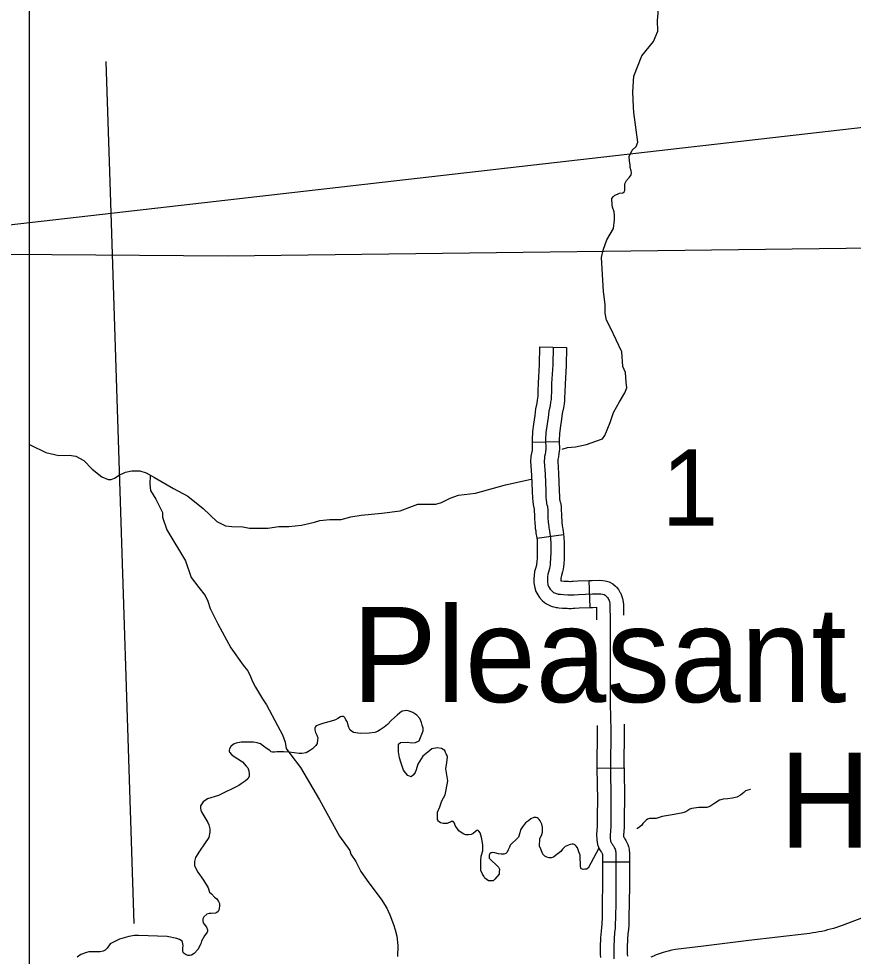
# Model space of a CAD drawing. Extents: x 1720274 to 1751788, y 372074 to 391887.
# Drawn here: x 1729981 to 1730713, y 376192 to 377014 of the extents above; entities that cross this region are included whole.
import ezdxf

# ---------------------------------------------------------------- set-up
doc = ezdxf.new("R2010")
doc.units = 0
for name, color, linetype in [('Level 10', 7, 'Continuous'), ('Level 24', 7, 'Continuous'), ('Level 32', 7, 'Continuous'), ('Level 35', 7, 'Continuous'), ('Level 43', 7, 'Continuous'), ('Level 5', 7, 'Continuous'), ('R_Draft', 7, 'Continuous')]:
    doc.layers.add(name, color=color, linetype=linetype)

msp = doc.modelspace()

# ---------------------------------------------------------------- linework, layer by layer
at = {"layer": 'Level 10'}
msp.add_lwpolyline([(1730737.54, 376231.42), (1730706.22, 376219.51), (1730703.68, 376218.58), (1730701.18, 376217.72), (1730698.66, 376216.91), (1730696.12, 376216.14), (1730693.57, 376215.41), (1730691.01, 376214.74), (1730688.43, 376214.11), (1730685.85, 376213.53), (1730683.25, 376213), (1730680.64, 376212.52), (1730678.03, 376212.08), (1730675.41, 376211.7), (1730672.74, 376211.35), (1730621.73, 376205.52), (1730582.16, 376200.57), (1730557.59, 376197.53), (1730554.34, 376197.01), (1730550.92, 376196.2), (1730548.79, 376195.57), (1730546.81, 376194.95), (1730544.89, 376194.34), (1730543.15, 376193.79), (1730540.43, 376192.82), (1730538.2, 376191.88), (1730535.95, 376190.94)], dxfattribs=at)
at = {"layer": 'Level 32'}
for p, q in [((1730438.24, 376726.42), (1730461.93, 376725.88)), ((1730431.72, 376642.9), (1730455.42, 376643.4)), ((1730435.82, 376558.63), (1730459.31, 376561.75)), ((1730482.61, 376497.72), (1730481.82, 376521.41)), ((1730488.61, 376356.58), (1730512.31, 376356.93)), ((1730493.33, 376274.54), (1730517.03, 376274.54))]:
    msp.add_line(p, q, dxfattribs=at)
for points in [[(1730438.24, 376726.42), (1730437.89, 376711.07), (1730436.91, 376694.72), (1730436.82, 376687.6), (1730436.56, 376683.28), (1730436.49, 376681.32), (1730436.22, 376679.69), (1730435.91, 376677.1), (1730434.74, 376671.99), (1730434.08, 376666.26), (1730432.76, 376658.67), (1730431.95, 376652.18), (1730431.68, 376644.93), (1730431.72, 376642.9)], [(1730450.08, 376726.15), (1730449.73, 376710.58), (1730448.75, 376694.29), (1730448.66, 376687.17), (1730448.4, 376682.72), (1730448.31, 376680.14), (1730447.95, 376678.01), (1730447.6, 376675.07), (1730446.44, 376670), (1730445.82, 376664.57), (1730444.48, 376656.92), (1730443.77, 376651.22), (1730443.54, 376644.83), (1730443.69, 376637.2), (1730443.38, 376634.01), (1730443.22, 376632.19), (1730442.66, 376630.28), (1730442.42, 376629), (1730442.26, 376625.9), (1730442.98, 376614.61), (1730443.62, 376599.97), (1730443.85, 376594.17), (1730444.01, 376591.78), (1730444.25, 376589.87), (1730444.41, 376589.08), (1730444.73, 376587.65), (1730445.05, 376586.85), (1730445.28, 376585.34), (1730445.36, 376583.91), (1730445.44, 376582), (1730445.52, 376580.01), (1730445.52, 376576.59), (1730445.84, 376572.69), (1730446.08, 376570.63), (1730446.24, 376568.72), (1730446.4, 376567.76), (1730446.55, 376566.57), (1730446.79, 376564.82), (1730447.51, 376560.61), (1730447.83, 376558.22), (1730448.06, 376553.77), (1730448.06, 376545.97), (1730447.91, 376540.96), (1730447.59, 376536.67), (1730447.43, 376534.92), (1730447.27, 376533.56), (1730446.87, 376531.89), (1730446, 376528.84), (1730445.5, 376526.98), (1730445.14, 376524.49), (1730445.05, 376522.86), (1730445.05, 376520.45), (1730445.59, 376517.51), (1730445.91, 376516.29)], [(1730461.93, 376725.88), (1730461.57, 376710.09), (1730460.6, 376693.86), (1730460.51, 376686.74), (1730460.23, 376682.16), (1730460.12, 376678.96), (1730459.68, 376676.32), (1730459.29, 376673.03), (1730458.14, 376668), (1730457.55, 376662.87), (1730456.21, 376655.16), (1730455.6, 376650.26), (1730455.39, 376644.74), (1730455.42, 376643.4)], [(1730431.72, 376642.9), (1730431.83, 376637.66), (1730431.58, 376635.12), (1730431.51, 376634.38), (1730431.12, 376633.03), (1730430.63, 376630.4), (1730430.4, 376625.83), (1730431.15, 376613.98), (1730431.78, 376599.47), (1730432.02, 376593.53), (1730432.21, 376590.65), (1730432.55, 376587.98), (1730432.81, 376586.63), (1730433.37, 376584.14), (1730433.5, 376583.81), (1730433.53, 376583.33), (1730433.6, 376581.52), (1730433.67, 376579.78), (1730433.67, 376576.11), (1730434.05, 376571.53), (1730434.28, 376569.46), (1730434.47, 376567.25), (1730434.68, 376566.01), (1730434.81, 376564.99), (1730435.08, 376563.03), (1730435.79, 376558.83), (1730435.82, 376558.62)], [(1730455.42, 376643.4), (1730455.56, 376636.73), (1730455.18, 376632.91), (1730454.92, 376629.99), (1730454.22, 376627.57), (1730454.13, 376625.97), (1730454.81, 376615.24), (1730455.45, 376600.47), (1730455.69, 376594.81), (1730455.81, 376592.91), (1730455.96, 376591.77), (1730456.01, 376591.52), (1730456.09, 376591.15), (1730456.54, 376590.01), (1730457.08, 376586.6), (1730457.2, 376584.48), (1730457.28, 376582.48), (1730457.37, 376580.25), (1730457.37, 376577.07), (1730457.63, 376573.86), (1730457.87, 376571.8), (1730458.01, 376570.18), (1730458.12, 376569.52), (1730458.3, 376568.15), (1730458.51, 376566.61), (1730459.23, 376562.38), (1730459.31, 376561.76)], [(1730435.82, 376558.63), (1730436.02, 376557.12), (1730436.21, 376553.45), (1730436.21, 376546.16), (1730436.07, 376541.59), (1730435.78, 376537.64), (1730435.64, 376536.14), (1730435.58, 376535.63), (1730435.41, 376534.9), (1730434.58, 376532.01), (1730433.87, 376529.38), (1730433.33, 376525.67), (1730433.2, 376523.19), (1730433.2, 376519.37), (1730434.01, 376514.95), (1730434.86, 376511.66), (1730436.57, 376508.82), (1730438.12, 376506.48), (1730440.61, 376503.75), (1730442.53, 376502.13), (1730444.24, 376500.95), (1730446.53, 376499.63), (1730448.5, 376498.97), (1730449.34, 376498.69), (1730450.84, 376498.24), (1730452.73, 376497.82), (1730454.05, 376497.68), (1730455.15, 376497.52), (1730458.35, 376497.27), (1730462.46, 376497.06), (1730464, 376496.97), (1730465.93, 376496.97), (1730467.59, 376497.05), (1730469.15, 376497.13), (1730472.91, 376497.4), (1730482.61, 376497.72)], [(1730459.31, 376561.75), (1730459.63, 376559.32), (1730459.91, 376554.08), (1730459.91, 376545.78), (1730459.74, 376540.34), (1730459.4, 376535.69), (1730459.22, 376533.69), (1730458.96, 376531.5), (1730458.34, 376528.89), (1730457.42, 376525.67), (1730457.13, 376524.59), (1730456.94, 376523.31), (1730456.9, 376522.53), (1730456.9, 376521.54), (1730456.96, 376521.2), (1730456.97, 376521.2), (1730457.76, 376521.09), (1730459.89, 376520.92), (1730463.73, 376520.72), (1730464.66, 376520.67), (1730465.34, 376520.67), (1730466.43, 376520.72), (1730467.74, 376520.79), (1730471.67, 376521.07), (1730481.82, 376521.41)], [(1730445.91, 376516.29), (1730446.59, 376515.15), (1730447.49, 376513.79), (1730448.85, 376512.3), (1730449.71, 376511.57), (1730450.57, 376510.98), (1730451.43, 376510.48), (1730452.25, 376510.21), (1730452.92, 376509.99), (1730453.83, 376509.71), (1730454.65, 376509.53), (1730455.51, 376509.44), (1730456.46, 376509.31), (1730459.12, 376509.09), (1730463.1, 376508.89), (1730464.33, 376508.82), (1730465.64, 376508.82), (1730467.01, 376508.89), (1730468.45, 376508.96), (1730472.29, 376509.23), (1730484.56, 376509.64), (1730490.53, 376509.78), (1730492.11, 376509.57), (1730493.48, 376509.37), (1730494.92, 376509.03), (1730495.67, 376508.61), (1730496.7, 376507.72), (1730497.25, 376507.17), (1730497.8, 376506.62), (1730498.28, 376505.66), (1730498.76, 376504.84), (1730499.17, 376504.01), (1730499.51, 376502.85), (1730499.79, 376501.34), (1730499.92, 376499.48), (1730499.99, 376496.87), (1730499.99, 376494.34), (1730500.06, 376491.45), (1730500.26, 376481.02), (1730500.26, 376436.39), (1730500.26, 376413.25), (1730500.63, 376389.73), (1730500.45, 376357.32), (1730500.87, 376328.9), (1730500.67, 376315.2), (1730500.67, 376305.47), (1730500.12, 376298.07), (1730500.19, 376294.85), (1730500.39, 376293.54), (1730500.53, 376292.72), (1730500.73, 376292.17), (1730501.01, 376291.62), (1730501.42, 376290.94), (1730501.9, 376290.25), (1730502.65, 376289.29), (1730502.99, 376288.54), (1730503.68, 376287.44), (1730504.09, 376286.62), (1730504.5, 376285.66), (1730504.77, 376284.84), (1730504.98, 376283.95), (1730505.05, 376283.13), (1730505.18, 376281.83), (1730505.25, 376280.39), (1730505.18, 376275.93), (1730505.18, 376253.46), (1730505.11, 376239.27), (1730504.84, 376225.57), (1730504.64, 376219.4), (1730504.5, 376216.25), (1730504.02, 376212.48), (1730503.54, 376207.06), (1730503.33, 376199.73), (1730503.33, 376193.63), (1730503.51, 376189.45)], [(1730481.82, 376521.41), (1730484.23, 376521.49), (1730491.16, 376521.65), (1730493.75, 376521.31), (1730495.73, 376521.01), (1730499.21, 376520.19), (1730502.47, 376518.4), (1730504.79, 376516.4), (1730505.63, 376515.55), (1730507.54, 376513.64), (1730508.71, 376511.3), (1730509.19, 376510.47), (1730510.24, 376508.37), (1730511.06, 376505.58), (1730511.56, 376502.84), (1730511.76, 376500.08), (1730511.84, 376497.03), (1730511.84, 376494.48), (1730511.91, 376491.71), (1730511.92, 376490.91)], [(1730482.61, 376497.72), (1730484.9, 376497.8), (1730488.11, 376497.87), (1730488.14, 376496.72), (1730488.14, 376494.19), (1730488.21, 376491.2), (1730488.3, 376486.79)], [(1730488.71, 376394.15), (1730488.78, 376389.67), (1730488.6, 376357.27), (1730488.61, 376356.57)], [(1730512.4, 376395.31), (1730512.48, 376389.79), (1730512.3, 376357.38), (1730512.31, 376356.93)], [(1730488.61, 376356.58), (1730489.02, 376328.9), (1730488.82, 376315.29), (1730488.82, 376305.91), (1730488.26, 376298.38), (1730488.36, 376293.79), (1730488.69, 376291.65), (1730489.03, 376289.64), (1730489.85, 376287.43), (1730490.61, 376285.92), (1730491.47, 376284.49), (1730492.37, 376283.2), (1730492.45, 376283.1), (1730492.53, 376282.93), (1730493.28, 376281.72), (1730493.36, 376280.92), (1730493.4, 376280.2), (1730493.33, 376276.02), (1730493.33, 376274.54)], [(1730512.31, 376356.93), (1730512.72, 376328.9), (1730512.51, 376315.11), (1730512.51, 376305.03), (1730511.98, 376297.75), (1730512, 376296.57), (1730512.85, 376295.49), (1730513.46, 376294.15), (1730514.03, 376293.24), (1730514.84, 376291.61), (1730515.59, 376289.87), (1730516.19, 376288.05), (1730516.72, 376285.78), (1730516.84, 376284.24), (1730517, 376282.73), (1730517.11, 376280.58), (1730517.03, 376275.84), (1730517.03, 376274.54)], [(1730493.33, 376274.54), (1730493.33, 376253.48), (1730493.27, 376239.42), (1730493, 376225.88), (1730492.79, 376219.85), (1730492.68, 376217.25), (1730492.24, 376213.75), (1730491.71, 376207.75), (1730491.49, 376199.9), (1730491.48, 376193.39), (1730491.6, 376190.69)], [(1730517.03, 376274.54), (1730517.03, 376253.43), (1730516.96, 376239.12), (1730516.69, 376225.25), (1730516.48, 376218.94), (1730516.32, 376215.24), (1730515.8, 376211.21), (1730515.38, 376206.37), (1730515.18, 376199.56), (1730515.18, 376193.87), (1730515.28, 376191.67)]]:
    msp.add_lwpolyline(points, dxfattribs=at)
at = {"layer": 'Level 35'}
for points in [[(1730501.9, 376851.24), (1730501.53, 376856.69), (1730503.02, 376858.55), (1730504.32, 376859.67), (1730506.74, 376860.6), (1730508.23, 376861.34), (1730511.21, 376861.53), (1730512.51, 376862.46), (1730512.89, 376863.58), (1730512.89, 376865.44), (1730512.89, 376867.31), (1730513.07, 376869.54), (1730514.56, 376872.34), (1730517.17, 376875.32), (1730518.47, 376877.37), (1730519.03, 376879.23), (1730518.66, 376880.91), (1730517.73, 376883.89), (1730517.73, 376885.94), (1730517.06, 376889.57), (1730516.85, 376893.52), (1730519.55, 376898.93), (1730522.88, 376902.26), (1730524.54, 376906.01), (1730520.8, 376932.02), (1730520.59, 376936.8), (1730520.17, 376950.12), (1730521.01, 376964.06), (1730528.07, 376981.96), (1730538.2, 376994.58), (1730542, 377003.6), (1730541.8, 377012.96), (1730542.84, 377026.07)], [(1730457.97, 376636.63), (1730462.62, 376638.03), (1730469.61, 376638.73), (1730479.39, 376640.83), (1730487.54, 376643.62), (1730493.36, 376645.72), (1730495.46, 376648.75), (1730500.12, 376659.94), (1730503.14, 376668.79), (1730508.5, 376678.35), (1730513.16, 376686.04), (1730514.79, 376690.47), (1730514.09, 376695.6), (1730513.62, 376703.99), (1730511.29, 376709.35), (1730510.36, 376722.17), (1730500.35, 376743.14), (1730496.86, 376749.9), (1730495.92, 376755.96), (1730495.69, 376763.65), (1730494.26, 376775.13), (1730492.53, 376804.79), (1730493.91, 376811.35), (1730497.36, 376820.32), (1730503.22, 376830.32), (1730503.9, 376837.91), (1730503.9, 376841.7), (1730503.56, 376844.81), (1730502.18, 376848.95), (1730501.9, 376851.24)], [(1729990.7, 376640.78), (1729991.83, 376640.11), (1730005.09, 376633.66), (1730016.37, 376630.97), (1730025.51, 376631.5), (1730031.42, 376630.61), (1730038.23, 376626.66), (1730045.57, 376619.13), (1730053.99, 376612.31), (1730059.55, 376609.98), (1730062.42, 376609.98), (1730065.28, 376611.24), (1730069.22, 376613.93), (1730074.78, 376616.62), (1730080.33, 376617.69), (1730087.38, 376617.59), (1730093.04, 376615.88), (1730100.22, 376611.95), (1730117.06, 376602.27), (1730129.42, 376595.45), (1730143.04, 376584.69), (1730154.86, 376573.21), (1730162.56, 376569.45), (1730168.12, 376568.91), (1730177.79, 376568.37), (1730183.7, 376567.47), (1730191.77, 376567.47), (1730199.83, 376567.47), (1730209.5, 376568.73), (1730218.28, 376568.91), (1730229.39, 376569.99), (1730240.68, 376572.5), (1730245.33, 376574.11), (1730254.11, 376574.83), (1730264.15, 376574.83), (1730272.57, 376577.34), (1730281.7, 376578.77), (1730299.8, 376580.57), (1730315.74, 376582.54), (1730326.63, 376586.76), (1730331.37, 376588.34), (1730336.53, 376588.46), (1730339.39, 376588.46), (1730343.33, 376588.28), (1730347.1, 376588.46), (1730352.29, 376589.89), (1730359.64, 376593.66), (1730367.16, 376596.17), (1730381.85, 376598.14), (1730408.4, 376605.34), (1730430.77, 376610.42)], [(1730096.39, 376613.61), (1730096.15, 376605.92), (1730096.87, 376600.4), (1730101.43, 376592.71), (1730107.19, 376581.18), (1730107.43, 376576.86), (1730111.03, 376565.81), (1730127.58, 376538.67), (1730132.62, 376524.02), (1730139.34, 376515.38), (1730144.73, 376508.24), (1730146.98, 376503.29), (1730149.23, 376496.76), (1730155.97, 376483.27), (1730167.43, 376462.34), (1730178.22, 376447.04), (1730182.04, 376442.32), (1730184.07, 376438.72), (1730186.31, 376432.87), (1730189.01, 376427.7), (1730195.08, 376417.57), (1730198.68, 376412.4), (1730208.12, 376394.17), (1730212.61, 376385.85), (1730214.86, 376379.55), (1730215.76, 376373.92), (1730220.03, 376368.53), (1730228.35, 376357.28), (1730244.98, 376328.93), (1730262.51, 376296.98), (1730271.73, 376284.61), (1730272.63, 376281.23), (1730277.12, 376274.93), (1730281.39, 376265.93), (1730288.36, 376256.03), (1730299.15, 376241.86), (1730304.32, 376233.76), (1730306.79, 376227.91), (1730309.94, 376219.59), (1730311.51, 376214.86), (1730312.86, 376209.24), (1730313.98, 376201.14), (1730313.53, 376191.47)], [(1730263.46, 376401.75), (1730261.11, 376400.29), (1730259.09, 376399.06), (1730254.39, 376397.71), (1730248.78, 376396.25), (1730245.31, 376395.02), (1730242.17, 376393.78), (1730241.27, 376392.77), (1730241.05, 376391.88), (1730240.94, 376390.42), (1730241.5, 376387.95), (1730242.73, 376385.82), (1730243.52, 376383.35), (1730243.29, 376381.56), (1730243.07, 376378.42), (1730241.83, 376376.51), (1730238.81, 376373.7), (1730236.23, 376372.02), (1730233.54, 376370.23), (1730229.51, 376369.55), (1730227.15, 376369.55), (1730218.54, 376370.71)], [(1730385.95, 376300), (1730384.94, 376301.57), (1730384.38, 376302.02), (1730383.82, 376302.25), (1730383.26, 376302.02), (1730381.91, 376301.01), (1730379.9, 376299.44), (1730378.1, 376298.55), (1730375.86, 376298.32), (1730373.51, 376298.32), (1730371.15, 376299.11), (1730367.23, 376301.8), (1730364.21, 376306.4), (1730363.42, 376308.53), (1730362.64, 376309.65), (1730362.41, 376309.88), (1730361.41, 376309.99), (1730361.07, 376309.99), (1730359.95, 376309.43), (1730358.16, 376308.75), (1730357.15, 376308.19), (1730355.58, 376308.19), (1730353.67, 376308.19), (1730351.21, 376308.87), (1730350.09, 376309.54), (1730349.53, 376310.32), (1730348.63, 376311.78), (1730348.52, 376312.68), (1730348.52, 376314.81), (1730348.63, 376318.18), (1730350.76, 376322.66), (1730352.55, 376327.94), (1730355.24, 376333.21), (1730356.36, 376337.58), (1730357.6, 376345.55), (1730355.91, 376356.09), (1730356.92, 376361.81), (1730357.26, 376364.28), (1730357.37, 376366.3), (1730357.15, 376367.76), (1730356.36, 376369.22), (1730355.69, 376370.56), (1730354.99, 376372.29), (1730353.59, 376373.07), (1730352.04, 376374.01), (1730348.3, 376374.63), (1730343.79, 376373.69), (1730340.21, 376370.89), (1730335.86, 376367.16), (1730331.35, 376360.31), (1730329.79, 376355.32), (1730329.02, 376352.83), (1730327.46, 376350.97), (1730325.44, 376349.1), (1730322.64, 376350.19), (1730320.77, 376352.21), (1730318.75, 376355.01), (1730316.42, 376361.86), (1730315.17, 376365.75), (1730314.55, 376371.2), (1730314.55, 376374.94), (1730314.55, 376377.9), (1730316.26, 376379.14), (1730322.64, 376379.45), (1730325.75, 376378.99), (1730329.48, 376379.3), (1730332.61, 376380.77), (1730336.08, 376389.41), (1730335.97, 376391.88), (1730335.29, 376394.57), (1730334.51, 376396.92), (1730333.05, 376400.18), (1730330.48, 376403.09), (1730327.11, 376405.67), (1730324.76, 376406.57), (1730322.97, 376406.91), (1730321.73, 376407.24), (1730319.61, 376407.02), (1730317.59, 376406.8), (1730315.57, 376405.23), (1730313.11, 376403.32), (1730308.18, 376398.83), (1730304.7, 376395.02), (1730301.8, 376392.84), (1730298.22, 376390.51), (1730296.04, 376388.95), (1730293.55, 376388.02), (1730288.57, 376387.55), (1730280.8, 376387.08), (1730275, 376387.95), (1730272.09, 376390.08), (1730270.97, 376392.44), (1730269.29, 376397.71), (1730268.28, 376399.17), (1730267.61, 376400.51), (1730267.16, 376401.19), (1730266.71, 376401.75), (1730266.26, 376402.08), (1730265.48, 376402.2), (1730264.69, 376402.2), (1730263.46, 376401.75)], [(1730218.54, 376370.71), (1730213.65, 376371.05), (1730210.18, 376371.05), (1730207.52, 376371.05), (1730205.65, 376370.78), (1730203.78, 376370.78), (1730202.72, 376371.05), (1730201.38, 376372.12), (1730199.25, 376373.72), (1730196.05, 376376.12), (1730193.38, 376377.99), (1730190.45, 376379.06), (1730187.25, 376379.59), (1730184.85, 376379.59), (1730180.85, 376379.59), (1730176.31, 376379.59), (1730172.05, 376378.79), (1730169.76, 376377.67), (1730167.24, 376375.71), (1730166.12, 376373.75), (1730165.84, 376372.63), (1730165.84, 376371.65), (1730165.98, 376370.67), (1730167.8, 376368.85), (1730170.18, 376366.89), (1730173.39, 376364.78), (1730177.59, 376362.26), (1730180.67, 376358.62), (1730182.07, 376357.08), (1730183.05, 376354.28), (1730183.47, 376351.76), (1730183.33, 376349.38), (1730182.21, 376347.28), (1730179.97, 376345.46), (1730176.33, 376343.08), (1730174.23, 376341.54), (1730156.61, 376332.86), (1730146.96, 376329.78), (1730142.9, 376327.26), (1730140.8, 376323.62), (1730140.66, 376321.66), (1730141.08, 376319.98), (1730141.92, 376317.74), (1730143.6, 376314.8), (1730145.28, 376312), (1730147.24, 376308.92), (1730148.08, 376306.96), (1730148.78, 376303.46), (1730148.78, 376300.65), (1730147.94, 376295.89), (1730144.3, 376290.43), (1730139.82, 376283.99), (1730136.19, 376278.25), (1730135.49, 376274.75), (1730135.49, 376271.11), (1730138.29, 376265.51), (1730143.32, 376258.51), (1730147.38, 376251.79), (1730148.5, 376248.01), (1730150.18, 376246.39), (1730152.87, 376243.4), (1730154.96, 376241.91), (1730156.6, 376239.67), (1730157.2, 376237.88), (1730157.2, 376235.78), (1730157.05, 376233.54), (1730156.75, 376232.05), (1730156.3, 376230.86), (1730155.11, 376229.96), (1730153.73, 376229.35), (1730149.92, 376229.07), (1730148.22, 376229.07), (1730146.1, 376228.5), (1730143.56, 376226.24), (1730142.71, 376224.55), (1730142.71, 376222.99), (1730143, 376221.01), (1730143.98, 376219.74), (1730145.82, 376217.05), (1730146.67, 376214.93), (1730146.81, 376213.8), (1730146.53, 376212.67), (1730144.27, 376209.7), (1730141.58, 376204.76), (1730141.02, 376202.49), (1730138.34, 376197.69), (1730135.23, 376194.01), (1730132.83, 376192.74), (1730131.28, 376192.32), (1730129.72, 376192.32), (1730128.17, 376192.88), (1730126.47, 376194.01), (1730125.49, 376195), (1730125.2, 376196.42), (1730125.2, 376198.68), (1730125.34, 376201.22), (1730125.2, 376202.64), (1730124.78, 376203.91), (1730124.5, 376204.76), (1730123.79, 376205.6), (1730122.1, 376206.45)], [(1730623.45, 376338.09), (1730622.96, 376338.03), (1730618.81, 376336.8), (1730617.36, 376335.23), (1730614.56, 376332.98), (1730611.19, 376331.41), (1730607.5, 376330.4), (1730603.01, 376329.84), (1730599.31, 376329.62), (1730596.18, 376328.61), (1730592.14, 376326.14), (1730587.55, 376323.11), (1730584.97, 376322.22), (1730581.72, 376322.1), (1730578.02, 376322.1), (1730571.97, 376321.43), (1730570.07, 376320.76), (1730566.7, 376318.51), (1730563.9, 376317.5), (1730556.39, 376316.16), (1730545.75, 376314.36), (1730540.48, 376312.57), (1730536.56, 376312.57), (1730534.65, 376312.57), (1730532.97, 376311.89), (1730531.63, 376311.11), (1730530.06, 376309.43), (1730528.94, 376308.08), (1730527.59, 376306.4), (1730525.02, 376304.38), (1730523.44, 376303.5)], [(1730490.34, 376286.43), (1730481, 376268.97), (1730479.54, 376268.18), (1730478.08, 376267.96), (1730476.4, 376267.85), (1730474.94, 376268.29), (1730474.38, 376269.19), (1730474.27, 376270.31), (1730474.05, 376271.77), (1730474.05, 376273.45), (1730473.82, 376277.04), (1730473.71, 376280.41), (1730472.7, 376283.21), (1730471.36, 376286.8), (1730470.24, 376288.26), (1730469.45, 376289.05), (1730468.56, 376289.61), (1730467.55, 376289.94), (1730466.76, 376289.94), (1730465.08, 376289.83), (1730463.74, 376289.27), (1730460.6, 376288.04), (1730458.36, 376285.57), (1730456.79, 376283.55), (1730452.31, 376279.96), (1730450.4, 376278.61), (1730448.27, 376277.94), (1730446.59, 376277.94), (1730444.69, 376278.5), (1730442.89, 376279.51), (1730441.21, 376281.31), (1730439.31, 376285.57), (1730438.08, 376288.37), (1730438.3, 376294.65), (1730440.2, 376298.58), (1730440.88, 376300.6), (1730440.88, 376302.62), (1730440.88, 376304.98), (1730440.2, 376307.67), (1730439.31, 376309.24), (1730438.75, 376310.47), (1730437.74, 376311.59), (1730436.96, 376312.49), (1730436.06, 376313.05), (1730435.16, 376313.39), (1730434.6, 376313.39), (1730433.14, 376313.39), (1730430.68, 376312.38), (1730428.44, 376310.58), (1730425.86, 376308.79), (1730423.17, 376305.31), (1730421.38, 376302.73), (1730421.04, 376300.04), (1730419.7, 376296.11), (1730417.01, 376293.65), (1730414.43, 376291.18), (1730412.53, 376289.16), (1730411.74, 376287.48), (1730410.62, 376285.01), (1730409.84, 376282.99), (1730408.49, 376281.75), (1730406.81, 376281.31), (1730404.46, 376281.19), (1730402.22, 376281.53), (1730398.97, 376282.32), (1730396.95, 376282.76), (1730395.72, 376282.32), (1730394.48, 376281.42), (1730393.92, 376280.3), (1730393.92, 376278.95), (1730394.03, 376277.83), (1730394.71, 376277.16), (1730396.5, 376275.14), (1730399.64, 376272.44), (1730402.1, 376269.98), (1730403, 376268.18), (1730402.78, 376265.6), (1730402.66, 376263.81), (1730399.08, 376259.43), (1730397.37, 376257.9)], [(1730397.37, 376257.9), (1730395.58, 376257.83), (1730393.34, 376257.83), (1730392.22, 376258.72), (1730390.21, 376260.18), (1730389.2, 376261.98), (1730388.08, 376263.66), (1730386.73, 376266.8), (1730386.62, 376269.6), (1730386.73, 376272.75), (1730386.73, 376275.33), (1730386.96, 376279.36), (1730388.52, 376284.3), (1730388.3, 376289.12), (1730387.63, 376294.73), (1730386.73, 376297.87), (1730385.95, 376300)], [(1730086.3, 376209.77), (1730082.82, 376209.86), (1730077.68, 376208.86), (1730069.57, 376206.79), (1730061.37, 376202.48), (1730058.72, 376198.75), (1730057.07, 376197.09), (1730055.24, 376196.26), (1730052.76, 376195.43), (1730050.44, 376195.43), (1730046.3, 376195.43), (1730042.82, 376195.6), (1730040.5, 376194.94), (1730035.7, 376193.11), (1730032.39, 376190.79)], [(1730122.1, 376206.45), (1730120, 376207.25), (1730111.48, 376208.9), (1730086.3, 376209.77)]]:
    msp.add_lwpolyline(points, dxfattribs=at)
at = {"layer": 'Level 43'}
msp.add_lwpolyline([(1729200.59, 376813.61), (1730164.47, 376806.25), (1730754.28, 376813.59), (1730918.4, 376815.11), (1730969.53, 376817.84), (1731015.15, 376817.22), (1731044.95, 376817.85), (1731072.79, 376813.84), (1731105.34, 376805.76), (1731157.29, 376794.1), (1731189.16, 376785.3), (1731231.58, 376775.44), (1731287.59, 376768.49), (1731330.37, 376768.83), (1731374.44, 376766.13)], dxfattribs=at)
at = {"layer": 'Level 5'}
for points in [[(1730057.58, 376976.76), (1730061.02, 376871.22)], [(1730061.02, 376871.22), (1730066.62, 376699), (1730082.2, 376220.43)]]:
    msp.add_lwpolyline(points, dxfattribs=at)
at = {"layer": 'R_Draft'}
msp.add_line((1737452.73, 377689.1), (1728670.65, 376684.18), dxfattribs=at)
msp.add_lwpolyline([(1729990.7, 381816.11), (1741847.55, 381816.11), (1741847.55, 374371.32), (1729990.7, 374371.32)], close=True, dxfattribs=at)

# ---------------------------------------------------------------- texts
at = {"layer": 'Level 24'}
for s, p in [('Pleasant', (1730273.61, 376414.7)), ('Hill', (1730648.47, 376286.86))]:
    msp.add_text(s, height=83.424, dxfattribs=at).set_placement(p)
at = {"layer": 'Level 5'}
msp.add_text('1', height=66.74, dxfattribs=at).set_placement((1730545.29, 376569.66))

doc.saveas('drawing.dxf')
